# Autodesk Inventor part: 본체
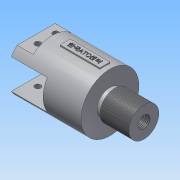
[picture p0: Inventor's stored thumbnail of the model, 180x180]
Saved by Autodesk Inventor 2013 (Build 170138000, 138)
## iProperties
Created: 2019-02
Part Number: 본체
Material: 알루미늄 6061
Document SubType Name: Modeling
Designer: Administrator
Density: 2.71 g/cm^3
Mass: 347.679 g
Surface Area: 294.887 cm^2
Volume: 128.295 cm^3
Author: Administrator
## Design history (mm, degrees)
sketch "스케치1"
  geometry: 1 further point
sketch "스케치2"
  geometry: L1 (-54, 0)-(-54, 29); L2 (-54, 29)-(20, 29); L3 (20, 29)-(20, 13); L4 (20, 13)-(25, 13); L5 (25, 13)-(25, 15); L6 (25, 15)-(54, 15); L7 (54, 15)-(54, 0); L8 (54, 0)-(-54, 0); 2 further points
  constraints: 16 end point, 4 parallel, 1 coincident, 1 horizontal, 1 midpoint, 1 vertical
  dimensions: "d2" = 30 diameter of L6 L8; "d3" = 26 diameter of L4 L8; "d4" = 58 diameter of L2 L8; "d5" = 74 distance of L1.end L2.end; "d6" = 34 horizontal distance of L6.end L2.end; "d7" = 5 distance of L3.end L4.end
revolve "회전1" sketch "스케치2" stored, may be unused: angle "d8" = 90 deg
sketch "스케치3"
  geometry: L1 (15, 38.25)-(-15, 38.25); L2 (-15, 38.25)-(-15, -38.036); L3 (-15, -38.036)-(15, -38.036); L4 (15, -38.036)-(15, 38.25); C1 r 29 at (0, 0) reference; 1 further point
  constraints: 8 end point, 2 parallel, 1 horizontal, 1 midpoint, 1 perpendicular, 1 vertical alignment
  dimensions: "d9" = 30 distance of L1.start L1.end
extrude "돌출1" cut sketch "스케치3" distance "d11" = 36; taper "d12" = 0 deg
sketch "스케치4"
  geometry: L1 (15, 24.819)-(15, -24.819) reference; L2 (-15, -24.819)-(-15, 24.819) reference; L3 (15, 24.819)-(15, -24.819) reference; L4 (39.665, 38.613)-(22, 38.613); L5 (22, 38.613)-(22, -30.913); L6 (22, -30.913)-(39.665, -30.913); L7 (39.665, -30.913)-(39.665, 38.613); L8 (-22, 58.316)-(-38.532, 58.316); L9 (-38.532, 58.316)-(-38.532, -42.69); L10 (-38.532, -42.69)-(-22, -42.69); L11 (-22, -42.69)-(-22, 58.316); A1 r 29 centre (0, 0) between (-15, 24.819) and (-15, -24.819) reference; A2 r 29 centre (0, 0) between (15, -24.819) and (15, 24.819) reference
  constraints: 16 end point, 4 parallel, 2 horizontal, 2 perpendicular
  dimensions: "d13" = 7 distance between parallel lines of L11 L2; "d14" = 7 distance between parallel lines of L5 L1
extrude "돌출2" cut sketch "스케치4" distance "d15" = 16; taper "d16" = 0 deg
sketch "스케치5"
  geometry: L1 (0, 0)-(0, 37.789) reference; L2 (36, 43.714)-(0, 43.714) reference; L3 (0, -5.925)-(36, -5.925) reference; L4 (36, 47.894)-(74, 47.894) reference; L5 (74, -10.106)-(74, 47.894) reference; L6 (0, 0)-(16, 0) reference; L7 (16, 0)-(16, 37.789) reference; L8 (16, 37.789)-(0, 37.789) reference; L9 (0, 37.789)-(0, 43.714) reference; L10 (0, 43.714)-(36, 43.714) reference; L11 (36, 43.714)-(36, 43.714) reference; L12 (36, 43.714)-(0, 43.714) reference; L13 (0, 43.714)-(0, 37.789) reference; L14 (0, 37.789)-(16, 37.789) reference; L15 (16, 37.789)-(16, 0) reference; L16 (16, 0)-(0, 0) reference; L17 (0, 0)-(0, -5.925) reference; L18 (0, -5.925)-(36, -5.925) reference; L19 (36, -5.925)-(36, -5.925) reference; L20 (36, -5.925)-(0, -5.925) reference; L21 (0, -5.925)-(0, 0) reference; L22 (36, -10.106)-(74, -10.106) reference; L23 (0, 18.894)-(108, 18.894); L24 (108, 3.894)-(108, 33.894) reference; L25 (79, 3.894)-(79, 33.894) reference; C1 r 3 at (9, 29.658); C2 r 3 at (9, 11.658); 1 further point
  constraints: 2 centre point, 2 end point, 2 midpoint, 1 parallel
  dimensions: "d17" = 6 diameter of C1; "d20" = 6 diameter of C2; "d21" = 18 distance of C2.centre C1.centre; "d22" = 9 distance from line of L1 C2.centre; "d25" = 29 distance between parallel lines of L23 L22
extrude "돌출3" cut sketch "스케치5" stored distance "d26" = 16; taper "d27" = 0 deg
sketch "스케치6"
  geometry: L1 (20, -29)-(-18, -29) reference; L2 (-18, -29)-(-18, 29) reference; L3 (-18, 29)-(20, 29) reference; L4 (20, 29)-(20, 13) reference; L5 (20, 13)-(25, 13) reference; L6 (25, 13)-(25, 15) reference; L7 (25, 15)-(54, 15) reference; L8 (54, 15)-(54, -15) reference; L9 (54, -15)-(25, -15) reference; L10 (25, -15)-(25, -13) reference; L11 (25, -13)-(20, -13) reference; L12 (20, -13)-(20, -29) reference; L13 (-18, 14)-(-15.35, 14); L14 (-15.35, 14)-(-15.35, 17); L15 (-15.35, 17)-(-10.65, 17); L16 (-10.65, 17)-(-10.65, 14); L17 (-10.65, 14)-(-6.35, 14); L18 (-6.35, 14)-(-6.35, 17); L19 (-6.35, 17)-(-1.65, 17); L20 (-1.65, 17)-(-1.65, 14); L21 (-1.65, 14)-(2, 14); L22 (2, 14)-(2, 16); L23 (2, 16)-(9, 16); L24 (9, 16)-(9, 4); L25 (9, 4)-(32, 4); L26 (-18, 0)-(54, 0); L27 (-18, 0)-(-18, 14); L28 (-13, 17)-(-13, 0); L29 (-4, 17)-(-4, 0); L30 (32, 4)-(32, 0); 1 further point
  constraints: 36 end point, 9 parallel, 6 perpendicular, 5 collinear, 4 midpoint, 4 point on line, 1 horizontal alignment
  dimensions: "d28" = 4.7 distance of L14.end L15.end; "d30" = 4.7 distance of L18.end L19.end; "d32" = 34 diameter of L15 L26; "d33" = 28 diameter of L17 L26; "d34" = 8 diameter of L25 L26; "d35" = 32 diameter of L23 L26; "d36" = 27 distance between parallel lines of L24 L2; "d37" = 20 distance between parallel lines of L2 L22; "d38" = 5 distance from line of L2 L28.start; "d39" = 9 distance between parallel lines of L28 L29; "d40" = 28 diameter of L13 L26; "d60" = 22 distance between parallel lines of L8 L30
revolve "회전2" sketch "스케치6" stored, may be unused: angle "d42" = 90 deg
feature "스레드1" dims "d43" = 10, "d44" = 0
node "작업 평면1"
sketch "스케치7"
  geometry: L1 (-25, 5)-(15, 5); L2 (15, 5)-(15, -5); L3 (15, -5)-(-25, -5); L4 (-25, -5)-(-25, 5); L5 (20, -29)-(20, 29) reference; 2 further points
  constraints: 8 end point, 2 parallel, 1 horizontal, 1 horizontal alignment, 1 midpoint, 1 perpendicular
  dimensions: "d46" = 40 distance of L1.start L1.end; "d48" = 10 distance of L3.end L1.start; "d49" = 5 distance between parallel lines of L5 L2
node "작업 평면2"
sketch "스케치8"
  geometry: 1 further point
sketch "스케치9"
  geometry: L1 (-25, 5)-(15, 5); L2 (15, 5)-(15, -5); L3 (15, -5)-(-25, -5); L4 (-25, -5)-(-25, 5); L5 (20, -29)-(20, 29) reference; 2 further points
  constraints: 8 end point, 2 parallel, 1 horizontal, 1 horizontal alignment, 1 midpoint, 1 perpendicular
  dimensions: "d51" = 5 distance between parallel lines of L5 L2; "d52" = 40 distance of L1.start L1.end; "d53" = 10 distance of L3.end L1.start
extrude "돌출4" join sketch "스케치9" stored distance "d54" = 16; taper "d55" = 0 deg
sketch "스케치10"
  geometry: L1 (-25, 5)-(15, 5) reference; L2 (-25, -5)-(-25, 5) reference; L3 (15, -5)-(-25, -5) reference; L4 (15, 5)-(15, -5) reference; 2 further points
  constraints: 1 other
  dimensions: "d56" = 20 distance from line of point (-5, 0) L2; "d57" = 5 distance from line of L3 point (-5, 0)
feature "엠보싱1" sketch "스케치10" dims "d58" = 0.5, "d59" = 0
sketch "스케치11"
  geometry: C1 r 15 at (0, 0) reference; 1 further point
  constraints: 1 coincident
hole "구멍1" sketch "스케치11" at (0, 0) diameter "d61" = 12.376; stored, may be unused: countersink angle "d65" = 82 deg, drill point angle "d67" = 118 deg; dims "d62" = 18, "d63" = 3.023, "d64" = 2, "d66" = 22
sketch "스케치12"
  geometry: 1 further point
sketch "스케치13"
  geometry: 1 further point
sketch "스케치14"
  geometry: 1 further point
node "솔리드1"
node "투영된 루프1"
node "투영된 루프2"
node "투영된 루프3"
node "투영된 루프4"
node "투영된 루프5"
node "절단 모서리 투영1"
